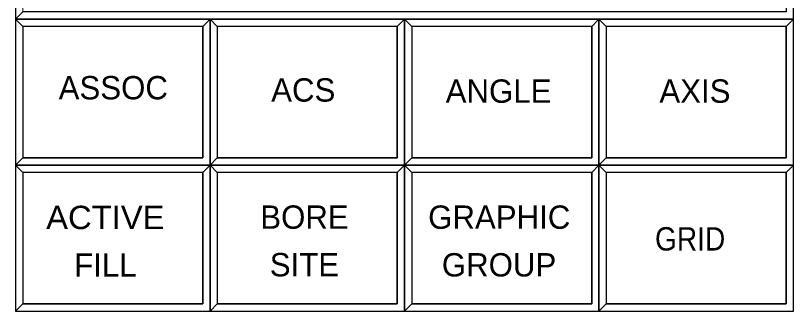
# Model space of a CAD drawing. Extents: x 95906.9 to 95918.9, y 90964.8 to 90972.9.
# Drawn here: x 95916.332 to 95917.932, y 90969.669 to 90970.269 of the extents above; entities that cross this region are included whole.
import ezdxf
from ezdxf.enums import TextEntityAlignment as Align

# ---------------------------------------------------------------- set-up
doc = ezdxf.new("R2010")
doc.units = 0
doc.header["$LTSCALE"] = 0.019
for name, color, linetype, lineweight in [('1', 7, 'Continuous', 25), ('11', 7, 'Continuous', 25), ('12', 7, 'Continuous', 25), ('2', 7, 'Continuous', 13), ('3', 7, 'Continuous', 25), ('4', 7, 'Continuous', 35), ('6', 7, 'Continuous', 35)]:
    doc.layers.add(name, color=color, linetype=linetype, lineweight=lineweight)

msp = doc.modelspace()

# ---------------------------------------------------------------- linework, layer by layer
at = {"layer": '1'}
for points in [[(95916.3323, 90970.2617), (95917.9323, 90970.2617), (95917.9323, 90970.3617), (95916.3323, 90970.3617)], [(95916.3323, 90969.9617), (95916.7323, 90969.9617), (95916.7323, 90970.2617), (95916.3323, 90970.2617)], [(95916.7323, 90969.9617), (95917.1323, 90969.9617), (95917.1323, 90970.2617), (95916.7323, 90970.2617)], [(95917.1323, 90969.9617), (95917.5323, 90969.9617), (95917.5323, 90970.2617), (95917.1323, 90970.2617)], [(95917.5323, 90969.9617), (95917.9323, 90969.9617), (95917.9323, 90970.2617), (95917.5323, 90970.2617)], [(95916.3323, 90969.6617), (95916.7323, 90969.6617), (95916.7323, 90969.9617), (95916.3323, 90969.9617)], [(95916.7323, 90969.6617), (95917.1323, 90969.6617), (95917.1323, 90969.9617), (95916.7323, 90969.9617)], [(95917.1323, 90969.6617), (95917.5323, 90969.6617), (95917.5323, 90969.9617), (95917.1323, 90969.9617)], [(95917.5323, 90969.6617), (95917.9323, 90969.6617), (95917.9323, 90969.9617), (95917.5323, 90969.9617)]]:
    msp.add_lwpolyline(points, close=True, dxfattribs=at)
at = {"layer": '11'}
for points in [[(95916.3473, 90969.9767), (95916.7173, 90969.9767), (95916.7173, 90970.2467), (95916.3473, 90970.2467)], [(95916.7473, 90969.9767), (95917.1173, 90969.9767), (95917.1173, 90970.2467), (95916.7473, 90970.2467)], [(95917.1473, 90969.9767), (95917.5173, 90969.9767), (95917.5173, 90970.2467), (95917.1473, 90970.2467)], [(95917.5473, 90969.9767), (95917.9173, 90969.9767), (95917.9173, 90970.2467), (95917.5473, 90970.2467)], [(95916.3473, 90969.6767), (95916.7173, 90969.6767), (95916.7173, 90969.9467), (95916.3473, 90969.9467)], [(95916.7473, 90969.6767), (95917.1173, 90969.6767), (95917.1173, 90969.9467), (95916.7473, 90969.9467)], [(95917.1473, 90969.6767), (95917.5173, 90969.6767), (95917.5173, 90969.9467), (95917.1473, 90969.9467)], [(95917.5473, 90969.6767), (95917.9173, 90969.6767), (95917.9173, 90969.9467), (95917.5473, 90969.9467)]]:
    msp.add_lwpolyline(points, close=True, dxfattribs=at)
at = {"layer": '12'}
msp.add_lwpolyline([(95917.5473, 90969.9767), (95917.9173, 90969.9767), (95917.9173, 90970.2467), (95917.5473, 90970.2467)], close=True, dxfattribs=at)
at = {"layer": '2'}
for points in [[(95916.3323, 90970.3617), (95916.3323, 90970.2617), (95916.3473, 90970.2767), (95916.3473, 90970.3467), (95917.9173, 90970.3467), (95917.9323, 90970.3617)], [(95916.3323, 90970.2617), (95916.3323, 90969.9617), (95916.3473, 90969.9767), (95916.3473, 90970.2467), (95916.7173, 90970.2467), (95916.7323, 90970.2617)], [(95916.7323, 90970.2617), (95916.7323, 90969.9617), (95916.7473, 90969.9767), (95916.7473, 90970.2467), (95917.1173, 90970.2467), (95917.1323, 90970.2617)], [(95917.1323, 90970.2617), (95917.1323, 90969.9617), (95917.1473, 90969.9767), (95917.1473, 90970.2467), (95917.5173, 90970.2467), (95917.5323, 90970.2617)], [(95917.5323, 90970.2617), (95917.5323, 90969.9617), (95917.5473, 90969.9767), (95917.5473, 90970.2467), (95917.9173, 90970.2467), (95917.9323, 90970.2617)], [(95916.3323, 90969.9617), (95916.3323, 90969.6617), (95916.3473, 90969.6767), (95916.3473, 90969.9467), (95916.7173, 90969.9467), (95916.7323, 90969.9617)], [(95916.7323, 90969.9617), (95916.7323, 90969.6617), (95916.7473, 90969.6767), (95916.7473, 90969.9467), (95917.1173, 90969.9467), (95917.1323, 90969.9617)], [(95917.1323, 90969.9617), (95917.1323, 90969.6617), (95917.1473, 90969.6767), (95917.1473, 90969.9467), (95917.5173, 90969.9467), (95917.5323, 90969.9617)], [(95917.5323, 90969.9617), (95917.5323, 90969.6617), (95917.5473, 90969.6767), (95917.5473, 90969.9467), (95917.9173, 90969.9467), (95917.9323, 90969.9617)]]:
    msp.add_lwpolyline(points, close=True, dxfattribs=at)
at = {"layer": '3'}
for points in [[(95916.3323, 90970.2617), (95917.9323, 90970.2617), (95917.9323, 90970.3617), (95917.9173, 90970.3467), (95917.9173, 90970.2767), (95916.3473, 90970.2767)], [(95916.3323, 90969.9617), (95916.7323, 90969.9617), (95916.7323, 90970.2617), (95916.7173, 90970.2467), (95916.7173, 90969.9767), (95916.3473, 90969.9767)], [(95916.7323, 90969.9617), (95917.1323, 90969.9617), (95917.1323, 90970.2617), (95917.1173, 90970.2467), (95917.1173, 90969.9767), (95916.7473, 90969.9767)], [(95917.1323, 90969.9617), (95917.5323, 90969.9617), (95917.5323, 90970.2617), (95917.5173, 90970.2467), (95917.5173, 90969.9767), (95917.1473, 90969.9767)], [(95917.5323, 90969.9617), (95917.9323, 90969.9617), (95917.9323, 90970.2617), (95917.9173, 90970.2467), (95917.9173, 90969.9767), (95917.5473, 90969.9767)], [(95916.3323, 90969.6617), (95916.7323, 90969.6617), (95916.7323, 90969.9617), (95916.7173, 90969.9467), (95916.7173, 90969.6767), (95916.3473, 90969.6767)], [(95916.7323, 90969.6617), (95917.1323, 90969.6617), (95917.1323, 90969.9617), (95917.1173, 90969.9467), (95917.1173, 90969.6767), (95916.7473, 90969.6767)], [(95917.1323, 90969.6617), (95917.5323, 90969.6617), (95917.5323, 90969.9617), (95917.5173, 90969.9467), (95917.5173, 90969.6767), (95917.1473, 90969.6767)], [(95917.5323, 90969.6617), (95917.9323, 90969.6617), (95917.9323, 90969.9617), (95917.9173, 90969.9467), (95917.9173, 90969.6767), (95917.5473, 90969.6767)]]:
    msp.add_lwpolyline(points, close=True, dxfattribs=at)
at = {"layer": '4'}
for p, q in [((95916.3473, 90970.2467), (95916.3323, 90970.2617)), ((95916.7473, 90970.2467), (95916.7323, 90970.2617)), ((95917.1473, 90970.2467), (95917.1323, 90970.2617)), ((95917.5473, 90970.2467), (95917.5323, 90970.2617)), ((95916.3473, 90969.9467), (95916.3323, 90969.9617)), ((95916.7473, 90969.9467), (95916.7323, 90969.9617)), ((95917.1473, 90969.9467), (95917.1323, 90969.9617)), ((95917.5473, 90969.9467), (95917.5323, 90969.9617))]:
    msp.add_line(p, q, dxfattribs=at)

# ---------------------------------------------------------------- texts
at = {"layer": '6'}
for s, p in [('ASSOC', (95916.5333, 90970.0969)), ('ACS', (95916.9241, 90970.0923)), ('ANGLE', (95917.3258, 90970.0899)), ('AXIS', (95917.7297, 90970.09)), ('BORE', (95916.9266, 90969.8309)), ('GRAPHIC', (95917.3272, 90969.8308)), ('FILL', (95916.517, 90969.7324)), ('SITE', (95916.9265, 90969.7331)), ('GROUP', (95917.3268, 90969.7328))]:
    msp.add_text(s, height=0.048, dxfattribs=at).set_placement(p, align=Align.CENTER)
for s, width, p in [('ACTIVE', 1.05, (95916.517, 90969.8302)), ('GRID', 0.9, (95917.7198, 90969.7862))]:
    msp.add_text(s, height=0.048, dxfattribs=dict(at, width=width)).set_placement(p, align=Align.CENTER)

doc.saveas('drawing.dxf')
